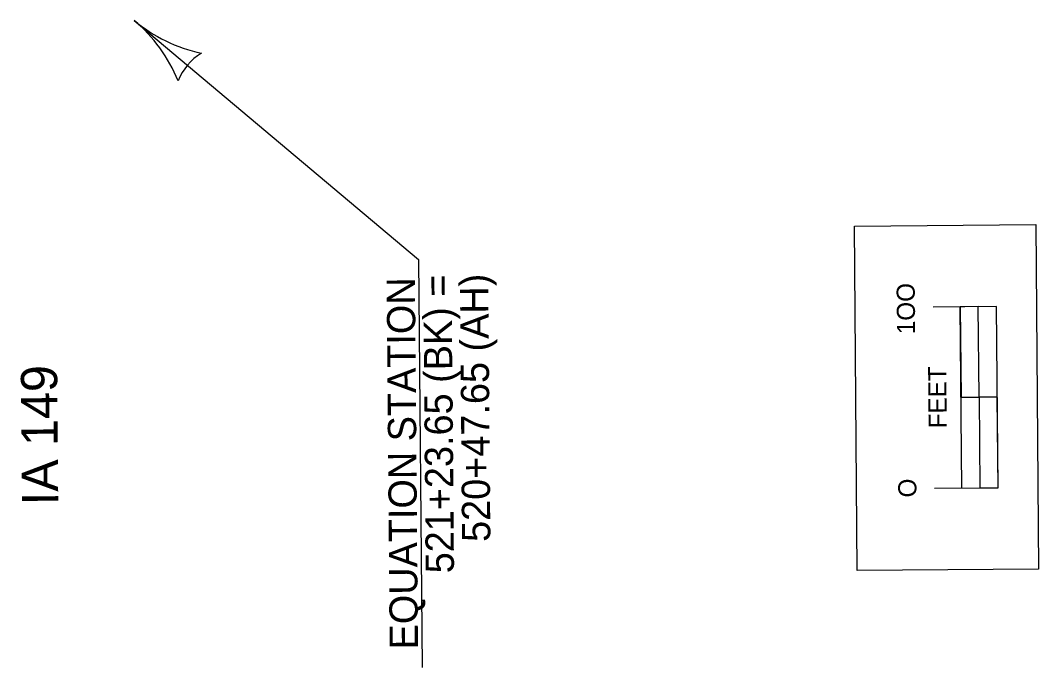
# Model space of a CAD drawing. Extents: x 23417754 to 23421386, y 6737896 to 6790956.
# Drawn here: x 23420825 to 23421386, y 6777261 to 6777618 of the extents above; entities that cross this region are included whole.
import ezdxf

# ---------------------------------------------------------------- set-up
doc = ezdxf.new("R2010")
doc.units = 0
for name, color, linetype in [('Curb', 7, 'Continuous'), ('Default', 7, 'Continuous'), ('dsnCellElements', 7, 'Continuous')]:
    doc.layers.add(name, color=color, linetype=linetype)

msp = doc.modelspace()

# ---------------------------------------------------------------- linework, layer by layer
at = {"layer": 'Curb'}
msp.add_line((23421363.43, 6777410.08), (23421343.43, 6777409.92), dxfattribs=at)
msp.add_line((23421363.43, 6777410.08), (23421343.43, 6777409.92), dxfattribs=at)
for points in [[(23421286.22, 6777314.44), (23421284.65, 6777504.44), (23421384.64, 6777505.26), (23421386.22, 6777315.27)], [(23421386.22, 6777315.27), (23421286.22, 6777314.44), (23421284.65, 6777504.44), (23421384.64, 6777505.26)], [(23421353.36, 6777410), (23421352.95, 6777460), (23421343.02, 6777459.92), (23421343.43, 6777409.92)], [(23421363.84, 6777360.09), (23421363.43, 6777410.08), (23421353.36, 6777410), (23421353.77, 6777360)]]:
    msp.add_lwpolyline(points, close=True, dxfattribs=at)
for points in [[(23421328.84, 6777359.8), (23421363.84, 6777360.09), (23421363.02, 6777460.08), (23421328.02, 6777459.79)], [(23421343.84, 6777359.92), (23421343.02, 6777459.92)]]:
    msp.add_lwpolyline(points, dxfattribs=at)
at = {"layer": 'dsnCellElements'}
msp.add_lwpolyline([(23420887.66, 6777617.92), (23421044.47, 6777486.1), (23421046.34, 6777260.88)], dxfattribs=at)
for centre, radius, start, end in [((23420832.94, 6777552.84), 85.03, 21.8757, 49.9482), ((23420942.37, 6777683.01), 85.03, 229.9482, 258.0207), ((23420942.23, 6777572.05), 32.84, 122.2149, 157.6816)]:
    msp.add_arc(centre, radius, start, end, dxfattribs=at)

# ---------------------------------------------------------------- texts
at = {"layer": 'Curb'}
for s, p in [('1OO', (23421318.14, 6777444.85)), ('1OO', (23421318.14, 6777444.85)), ('FEET', (23421335.57, 6777392.92)), ('O', (23421318.88, 6777354.79)), ('O', (23421318.88, 6777354.79))]:
    msp.add_text(s, height=10, rotation=90.4739, dxfattribs=at).set_placement(p)
at = {"layer": 'Default'}
msp.add_text('IA 149', height=20, rotation=90.4739, dxfattribs=at).set_placement((23420845.86, 6777350.52))
at = {"layer": 'dsnCellElements'}
for s, p in [('EQUATION STATION', (23421044.14, 6777271.01)), ('521+23.65 (BK) = ', (23421063.99, 6777312.98)), ('520+47.65 (AH)', (23421084.04, 6777330.3))]:
    msp.add_text(s, height=15.6048, rotation=90.4739, dxfattribs=at).set_placement(p)

doc.saveas('drawing.dxf')
